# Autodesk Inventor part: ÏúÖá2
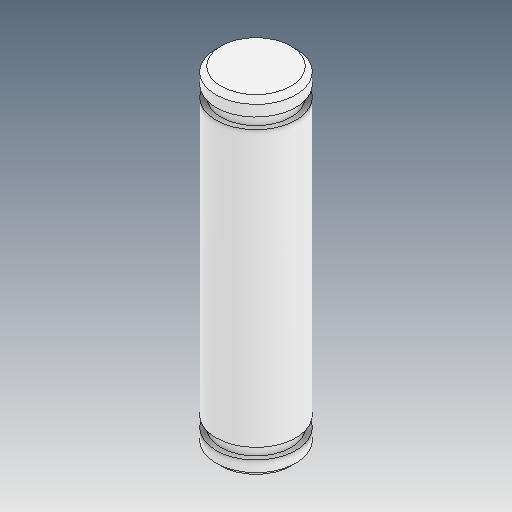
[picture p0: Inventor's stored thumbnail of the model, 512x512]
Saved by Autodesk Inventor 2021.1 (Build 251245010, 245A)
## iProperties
Created: 2021-05
Part Number: ÏúÖá2
Material: Ogólny
Document SubType Name: Modeling
Designer: user
Density: 1 g/cm^3
Appearance: Domyślna
Author: user
Revision Number: ÈÎºÎ
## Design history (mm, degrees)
feature "ÊäÈë1"
node "Bryła1"
